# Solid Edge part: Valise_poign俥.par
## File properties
Author: Bernard DUMAS
Template: Normal.par
Last saved by: FR026244
Revision: 16
Application: Solid Edge
Material: Bois, Frêne
Style de face: Jaune kaki
Style de remplissage: Liège
Style virtuel: Frêne verni
Coef. of Thermal Exp: 0.0
Thermal Conductivity: 0.0
Specific Heat: 0.0
Modulus of Elasticity: 0.0
Poission's Ratio: 0.0
Yield Stress: 0.0
Ultimate Stress: 0.0
Elongation: 0.0
Densité: 460.000 kg/m^3
Précision: 0.9900
Document Number: 15
Revision: a
Project Name: Slamson
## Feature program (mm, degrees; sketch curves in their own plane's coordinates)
sketch for "unnamed Protrusion 1" plane through (0, 0, 0) normal (0, -1, 0) x-axis (1, 0, 0)
  arc centre (-77.3438, 0) radius 22.6562 from (-80, 22.5) to (-80, -22.5) ccw
  line (-80, -22.5) -> (-80, -9)
  arc centre (0.4674, 636) radius 650 from (-80, -9) to (0, -13.9998) ccw
  line (0, 13.9998) -> (0, -13.9998)
  arc centre (0.4674, -636) radius 650 from (-80, 9) to (0, 13.9998) cw
  line (-80, 22.5) -> (-80, 9)
extrude "unnamed Protrusion 1" add finite 9 along +normal
mirror "unnamed Mirror 1" of "unnamed Protrusion 1" about plane through (0, 0, 0) normal (1, 0, 0)
extrude "unnamed Protrusion 2" add finite 9
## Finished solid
Body 1: solid body, 12 faces, 30 edges, 20 vertices.
  Faces by surface: cylinder 6, plane 6
  Edges by curve: line 18, circle 12
Bounding box of the edges (mm): 200.000 x 9.000 x 45.000, from (-100, -9, -22.5) to (100, 0, 22.5).
Cylindrical faces by radius (mm): R22.6562 x2, R650 x4
Planar faces by outward normal: +x 2, +y 1, -x 2, -y 1
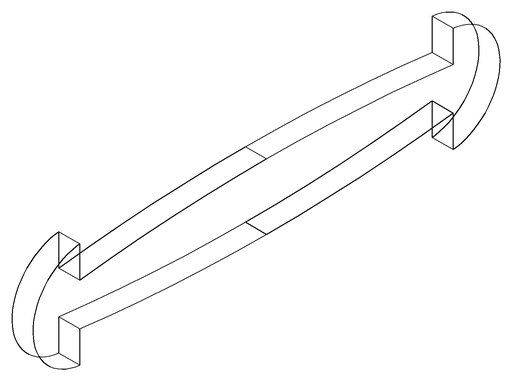
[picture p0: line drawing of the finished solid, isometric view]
